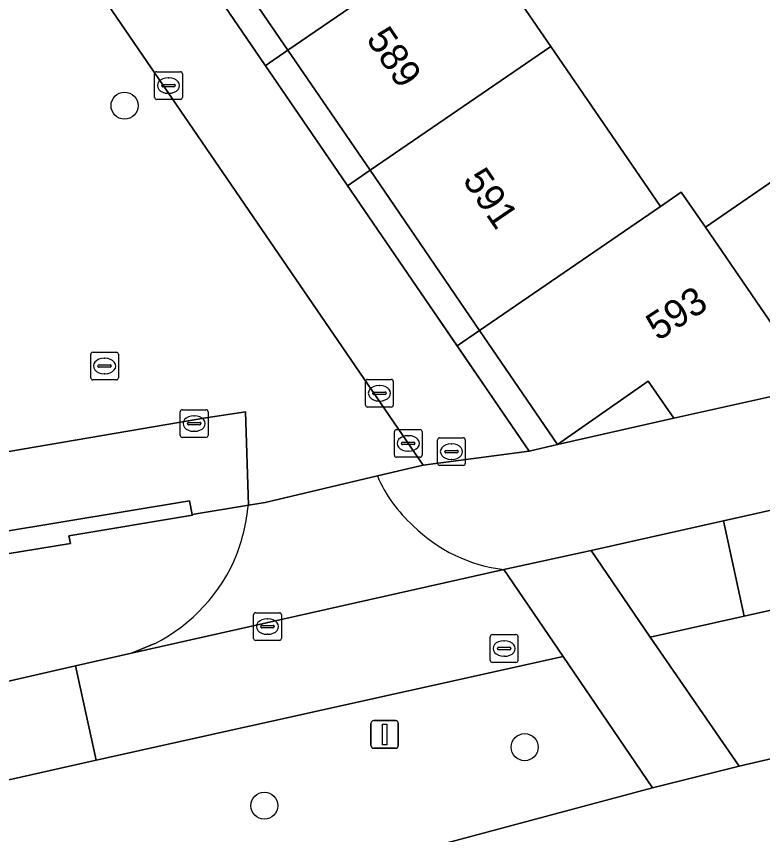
# Model space of a CAD drawing. Extents: x 155275 to 156265, y 382654 to 383635.
# Drawn here: x 155784.06 to 155810.99, y 383184.9 to 383214.43 of the extents above; entities that cross this region are included whole.
import ezdxf

# ---------------------------------------------------------------- set-up
doc = ezdxf.new("R2010")
doc.units = 0
for name, color, linetype in [('IMGEO_Berm_groen', 7, 'Continuous'), ('IMGEO_Boom', 7, 'Continuous'), ('IMGEO_Erf', 7, 'Continuous'), ('IMGEO_Fietspad_gesloten', 7, 'Continuous'), ('IMGEO_Kolk', 7, 'Continuous'), ('IMGEO_Pand', 7, 'Continuous'), ('IMGEO_Pand_nummerreeks', 7, 'Continuous'), ('IMGEO_Pand_overbouw', 7, 'Continuous'), ('IMGEO_Rijbaan_lokaal_gesloten', 7, 'Continuous'), ('IMGEO_Rijbaan_lokaal_open', 7, 'Continuous'), ('IMGEO_Rioolput', 7, 'Continuous'), ('IMGEO_Verkeersbordpaal', 7, 'Continuous'), ('IMGEO_Voetpad_op_trap', 7, 'Continuous'), ('IMGEO_Voetpad_open', 7, 'Continuous')]:
    doc.layers.add(name, color=color, linetype=linetype)

msp = doc.modelspace()

# ---------------------------------------------------------------- linework, layer by layer
at = {"layer": 'IMGEO_Berm_groen'}
msp.add_lwpolyline([(155848.276, 383195.813), (155845.025, 383200.548), (155840.331, 383199.496), (155810.33, 383192.781), (155806.938, 383192.022), (155810.141, 383187.373), (155824.371, 383190.683)], close=True, dxfattribs=at)
for points in [[(155807.023, 383186.593), (155803.798, 383191.327), (155786.939, 383187.587), (155780.617, 383186.169), (155774.297, 383184.74), (155766.281, 383182.536), (155758.269, 383180.313), (155752.351, 383178.024)], [(155758.942, 383174.226), (155784.144, 383180.465), (155807.023, 383186.593)]]:
    msp.add_lwpolyline(points, dxfattribs=at)
at = {"layer": 'IMGEO_Boom'}
for centre in [(155787.962, 383211.208), (155802.404, 383188.058), (155793.007, 383185.946)]:
    msp.add_circle(centre, 0.489, dxfattribs=at)
at = {"layer": 'IMGEO_Erf'}
for points in [[(155796.822, 383208.878), (155793.858, 383213.211), (155790.894, 383217.545), (155787.93, 383221.878), (155784.96, 383226.22), (155781.602, 383231.129), (155777.993, 383236.404), (155777.166, 383235.849), (155802.561, 383198.744), (155803.59, 383198.984), (155800.774, 383203.1)], [(155803.59, 383198.984), (155807.785, 383199.931), (155806.855, 383201.265)]]:
    msp.add_lwpolyline(points, close=True, dxfattribs=at)
msp.add_lwpolyline([(155800.38, 383217.68), (155803.347, 383213.349), (155807.304, 383207.574), (155808.057, 383208.09), (155808.925, 383206.823), (155812.132, 383209.02), (155812.697, 383208.195), (155816.162, 383210.569), (155817.448, 383208.691), (155821.408, 383211.404), (155821.973, 383210.579), (155824.618, 383212.391), (155825.438, 383212.953), (155823.731, 383215.445)], dxfattribs=at)
at = {"layer": 'IMGEO_Fietspad_gesloten'}
msp.add_lwpolyline([(155890.991, 383205.663), (155886.832, 383204.488), (155883.25, 383203.59), (155879.663, 383202.712), (155851.768, 383196.574), (155848.276, 383195.813), (155824.371, 383190.683), (155810.141, 383187.373), (155807.023, 383186.593), (155784.144, 383180.465), (155758.942, 383174.226)], dxfattribs=at)
at = {"layer": 'IMGEO_Kolk'}
for p, q in [((155789.048, 383211.508), (155789.048, 383212.36)), ((155789.123, 383212.434), (155789.975, 383212.434)), ((155790.049, 383212.36), (155790.049, 383211.508)), ((155789.536, 383212.214), (155789.561, 383212.214)), ((155789.307, 383211.928), (155789.307, 383211.94)), ((155789.745, 383211.891), (155789.347, 383211.891)), ((155789.35, 383211.977), (155789.748, 383211.977)), ((155789.791, 383211.94), (155789.791, 383211.928)), ((155789.559, 383211.654), (155789.534, 383211.654)), ((155789.975, 383211.434), (155789.123, 383211.434)), ((155786.815, 383202.312), (155787.667, 383202.312)), ((155786.74, 383201.386), (155786.74, 383202.238)), ((155787.228, 383202.092), (155787.253, 383202.092)), ((155787.741, 383202.238), (155787.741, 383201.386)), ((155786.999, 383201.806), (155786.999, 383201.818)), ((155787.437, 383201.769), (155787.039, 383201.769)), ((155787.042, 383201.855), (155787.44, 383201.855)), ((155787.483, 383201.818), (155787.483, 383201.806)), ((155787.251, 383201.532), (155787.226, 383201.532)), ((155787.667, 383201.312), (155786.815, 383201.312)), ((155796.66, 383200.404), (155796.66, 383201.256)), ((155796.735, 383201.33), (155797.587, 383201.33)), ((155797.148, 383201.11), (155797.173, 383201.11)), ((155797.661, 383201.256), (155797.661, 383200.404)), ((155796.919, 383200.824), (155796.919, 383200.836)), ((155796.962, 383200.873), (155797.36, 383200.873)), ((155797.403, 383200.836), (155797.403, 383200.824)), ((155797.357, 383200.787), (155796.959, 383200.787)), ((155797.171, 383200.55), (155797.146, 383200.55)), ((155790.048, 383200.236), (155790.9, 383200.236)), ((155797.587, 383200.33), (155796.735, 383200.33)), ((155789.973, 383199.31), (155789.973, 383200.162)), ((155790.461, 383200.016), (155790.486, 383200.016)), ((155790.974, 383200.162), (155790.974, 383199.31)), ((155790.232, 383199.73), (155790.232, 383199.742)), ((155790.67, 383199.693), (155790.272, 383199.693)), ((155790.275, 383199.779), (155790.673, 383199.779)), ((155790.716, 383199.742), (155790.716, 383199.73)), ((155790.484, 383199.456), (155790.459, 383199.456)), ((155790.9, 383199.236), (155790.048, 383199.236)), ((155792.696, 383192.91), (155793.548, 383192.91)), ((155792.621, 383191.984), (155792.621, 383192.836)), ((155793.109, 383192.69), (155793.134, 383192.69)), ((155793.622, 383192.836), (155793.622, 383191.984)), ((155792.88, 383192.404), (155792.88, 383192.416)), ((155793.318, 383192.367), (155792.92, 383192.367)), ((155792.923, 383192.453), (155793.321, 383192.453)), ((155793.364, 383192.416), (155793.364, 383192.404)), ((155793.132, 383192.13), (155793.107, 383192.13)), ((155793.548, 383191.91), (155792.696, 383191.91))]:
    msp.add_line(p, q, dxfattribs=at)
for points in [[(155789.048, 383211.508), (155789.048, 383212.36)], [(155789.123, 383212.434), (155789.975, 383212.434)], [(155790.049, 383212.36), (155790.049, 383211.508)], [(155789.975, 383211.434), (155789.123, 383211.434)], [(155786.815, 383202.312), (155787.667, 383202.312)], [(155786.74, 383201.386), (155786.74, 383202.238)], [(155787.741, 383202.238), (155787.741, 383201.386)], [(155787.667, 383201.312), (155786.815, 383201.312)], [(155796.66, 383200.404), (155796.66, 383201.256)], [(155796.735, 383201.33), (155797.587, 383201.33)], [(155797.661, 383201.256), (155797.661, 383200.404)], [(155790.048, 383200.236), (155790.9, 383200.236)], [(155797.587, 383200.33), (155796.735, 383200.33)], [(155789.973, 383199.31), (155789.973, 383200.162)], [(155790.974, 383200.162), (155790.974, 383199.31)], [(155790.9, 383199.236), (155790.048, 383199.236)], [(155792.696, 383192.91), (155793.548, 383192.91)], [(155792.621, 383191.984), (155792.621, 383192.836)], [(155793.622, 383192.836), (155793.622, 383191.984)], [(155793.548, 383191.91), (155792.696, 383191.91)]]:
    msp.add_lwpolyline(points, dxfattribs=at)
for centre, radius, start, end in [((155789.125, 383212.358), 0.0765, 91.552, 178.448), ((155789.125, 383212.358), 0.0765, 91.552, 178.448), ((155789.973, 383212.358), 0.0765, 1.552, 88.448), ((155789.973, 383212.358), 0.0765, 1.552, 88.448), ((155789.347, 383211.937), 0.0403, 85.8775, 175.7526), ((155789.344, 383211.927), 0.0366, 178.938, 274.7102), ((155789.748, 383211.934), 0.043, 264.8664, 352.4533), ((155789.752, 383211.939), 0.0386, 1.7309, 96.639), ((155789.125, 383211.51), 0.0765, 181.552, 268.448), ((155789.125, 383211.51), 0.0765, 181.552, 268.448), ((155789.973, 383211.51), 0.0765, 271.552, 358.448), ((155789.973, 383211.51), 0.0765, 271.552, 358.448), ((155786.817, 383202.236), 0.0765, 91.552, 178.448), ((155786.817, 383202.236), 0.0765, 91.552, 178.448), ((155787.665, 383202.236), 0.0765, 1.552, 88.448), ((155787.665, 383202.236), 0.0765, 1.552, 88.448), ((155787.039, 383201.815), 0.0403, 85.8775, 175.7526), ((155787.036, 383201.805), 0.0366, 178.938, 274.7102), ((155787.44, 383201.812), 0.043, 264.8664, 352.4533), ((155787.444, 383201.817), 0.0386, 1.7309, 96.639), ((155786.817, 383201.388), 0.0765, 181.552, 268.448), ((155786.817, 383201.388), 0.0765, 181.552, 268.448), ((155787.665, 383201.388), 0.0765, 271.552, 358.448), ((155787.665, 383201.388), 0.0765, 271.552, 358.448), ((155796.737, 383201.254), 0.0765, 91.552, 178.448), ((155796.737, 383201.254), 0.0765, 91.552, 178.448), ((155797.585, 383201.254), 0.0765, 1.552, 88.448), ((155797.585, 383201.254), 0.0765, 1.552, 88.448), ((155796.959, 383200.833), 0.0403, 85.8775, 175.7526), ((155796.956, 383200.823), 0.0366, 178.938, 274.7102), ((155797.36, 383200.83), 0.043, 264.8664, 352.4533), ((155797.364, 383200.835), 0.0386, 1.7309, 96.639), ((155790.05, 383200.16), 0.0765, 91.552, 178.448), ((155790.05, 383200.16), 0.0765, 91.552, 178.448), ((155790.898, 383200.16), 0.0765, 1.552, 88.448), ((155790.898, 383200.16), 0.0765, 1.552, 88.448), ((155796.737, 383200.406), 0.0765, 181.552, 268.448), ((155796.737, 383200.406), 0.0765, 181.552, 268.448), ((155797.585, 383200.406), 0.0765, 271.552, 358.448), ((155797.585, 383200.406), 0.0765, 271.552, 358.448), ((155790.272, 383199.739), 0.0403, 85.8775, 175.7526), ((155790.269, 383199.729), 0.0366, 178.938, 274.7102), ((155790.673, 383199.736), 0.043, 264.8664, 352.4533), ((155790.677, 383199.741), 0.0386, 1.7309, 96.639), ((155790.05, 383199.312), 0.0765, 181.552, 268.448), ((155790.05, 383199.312), 0.0765, 181.552, 268.448), ((155790.898, 383199.312), 0.0765, 271.552, 358.448), ((155790.898, 383199.312), 0.0765, 271.552, 358.448), ((155792.698, 383192.834), 0.0765, 91.552, 178.448), ((155792.698, 383192.834), 0.0765, 91.552, 178.448), ((155793.546, 383192.834), 0.0765, 1.552, 88.448), ((155793.546, 383192.834), 0.0765, 1.552, 88.448), ((155792.92, 383192.413), 0.0403, 85.8775, 175.7526), ((155792.917, 383192.403), 0.0366, 178.938, 274.7102), ((155793.321, 383192.41), 0.043, 264.8664, 352.4533), ((155793.325, 383192.415), 0.0386, 1.7309, 96.639), ((155792.698, 383191.986), 0.0765, 181.552, 268.448), ((155792.698, 383191.986), 0.0765, 181.552, 268.448), ((155793.546, 383191.986), 0.0765, 271.552, 358.448), ((155793.546, 383191.986), 0.0765, 271.552, 358.448)]:
    msp.add_arc(centre, radius, start, end, dxfattribs=at)
for centre, major_axis, ratio, start_param, end_param in [((155789.535, 383211.934), (-0.387, 0.002), 0.722429, 4.712389, 7.853982), ((155789.56, 383211.934), (-0.39, 0.002), 0.717154, 1.570796, 4.712389), ((155787.227, 383201.812), (-0.387, 0.002), 0.722429, 4.712389, 7.853982), ((155787.252, 383201.812), (-0.39, 0.002), 0.717154, 1.570796, 4.712389), ((155797.147, 383200.83), (-0.387, 0.002), 0.722429, 4.712389, 7.853982), ((155797.172, 383200.83), (-0.39, 0.002), 0.717154, 1.570796, 4.712389), ((155790.46, 383199.736), (-0.387, 0.002), 0.722429, 4.712389, 7.853982), ((155790.485, 383199.736), (-0.39, 0.002), 0.717154, 1.570796, 4.712389), ((155793.108, 383192.41), (-0.387, 0.002), 0.722429, 4.712389, 7.853982), ((155793.133, 383192.41), (-0.39, 0.002), 0.717154, 1.570796, 4.712389)]:
    msp.add_ellipse(centre, major_axis=major_axis, ratio=ratio, start_param=start_param, end_param=end_param, dxfattribs=at)
at = {"layer": 'IMGEO_Pand'}
for points in [[(155793.858, 383213.211), (155800.38, 383217.68), (155797.413, 383222.011), (155790.894, 383217.545)], [(155793.858, 383213.211), (155796.822, 383208.878), (155803.347, 383213.349), (155800.38, 383217.68)], [(155803.347, 383213.349), (155796.822, 383208.878), (155800.774, 383203.1), (155807.304, 383207.574)], [(155817.448, 383208.691), (155816.162, 383210.569), (155812.697, 383208.195), (155812.132, 383209.02), (155808.925, 383206.823), (155812.872, 383201.064), (155816.423, 383203.531), (155817.361, 383202.086), (155821.253, 383202.95)], [(155808.925, 383206.823), (155808.057, 383208.09), (155807.304, 383207.574), (155800.774, 383203.1), (155803.59, 383198.984), (155806.855, 383201.265), (155807.785, 383199.931), (155812.872, 383201.064)]]:
    msp.add_lwpolyline(points, close=True, dxfattribs=at)
at = {"layer": 'IMGEO_Pand_overbouw'}
for points in [[(155793.858, 383213.211), (155790.894, 383217.545), (155790.077, 383216.985), (155793.042, 383212.652)], [(155793.858, 383213.211), (155793.042, 383212.652), (155796.007, 383208.32), (155796.822, 383208.878)], [(155800.774, 383203.1), (155796.822, 383208.878), (155796.007, 383208.32), (155799.961, 383202.543)], [(155800.774, 383203.1), (155799.961, 383202.543), (155802.561, 383198.744), (155803.59, 383198.984)], [(155803.59, 383198.984), (155807.785, 383199.931), (155806.855, 383201.265)]]:
    msp.add_lwpolyline(points, close=True, dxfattribs=at)
at = {"layer": 'IMGEO_Rijbaan_lokaal_gesloten'}
msp.add_lwpolyline([(155840.331, 383199.496), (155839.534, 383202.939), (155809.577, 383196.225), (155810.33, 383192.781)], close=True, dxfattribs=at)
msp.add_lwpolyline([(155752.351, 383178.024), (155758.269, 383180.313), (155766.281, 383182.536), (155774.297, 383184.74), (155780.617, 383186.169), (155786.939, 383187.587), (155786.191, 383190.995), (155778.526, 383189.242), (155770.862, 383187.481), (155761.516, 383184.966), (155752.173, 383182.442)], dxfattribs=at)
at = {"layer": 'IMGEO_Rijbaan_lokaal_open'}
for points in [[(155789.533, 383282.828), (155777.762, 383266.885), (155770.477, 383257.018), (155750.942, 383230.559), (155753.136, 383227.355), (155767.095, 383206.967), (155771.224, 383200.936), (155773.915, 383197.049), (155790.895, 383199.943), (155792.328, 383200.159), (155792.43, 383196.787), (155793.032, 383196.885), (155797.086, 383197.846), (155798.734, 383198.236), (155786.907, 383215.526), (155772.43, 383236.689), (155783.237, 383244.091), (155793.514, 383251.129), (155807.738, 383260.872), (155811.353, 383255.588), (155821.26, 383241.107), (155827.482, 383232.012), (155843.488, 383208.615)], [(155797.086, 383197.846), (155793.032, 383196.885)], [(155793.032, 383196.885), (155792.43, 383196.787)], [(155788.207, 383191.448), (155801.654, 383194.468)], [(155789.06, 383191.794), (155788.207, 383191.448)]]:
    msp.add_lwpolyline(points, dxfattribs=at)
for points in [[(155804.8, 383195.157), (155806.938, 383192.022), (155810.33, 383192.781), (155809.577, 383196.225)], [(155801.654, 383194.468), (155788.207, 383191.448), (155786.191, 383190.995), (155786.939, 383187.587), (155803.798, 383191.327)]]:
    msp.add_lwpolyline(points, close=True, dxfattribs=at)
for centre, radius, start, end in [((155801.701, 383199.811), 5.016, 203.058, 228.5824), ((155784.943, 383197.609), 7.532, 339.8726, 353.7365), ((155802.297, 383199.973), 5.542, 225.0712, 263.3362), ((155786.198, 383197.385), 6.281, 297.1127, 337.8551)]:
    msp.add_arc(centre, radius, start, end, dxfattribs=at)
at = {"layer": 'IMGEO_Rioolput'}
for p, q in [((155797.701, 383198.593), (155797.701, 383199.445)), ((155797.776, 383199.519), (155798.628, 383199.519)), ((155798.702, 383199.445), (155798.702, 383198.593)), ((155798.003, 383199.062), (155798.401, 383199.062)), ((155798.189, 383199.299), (155798.214, 383199.299)), ((155799.259, 383198.298), (155799.259, 383199.15)), ((155799.334, 383199.224), (155800.186, 383199.224)), ((155800.26, 383199.15), (155800.26, 383198.298)), ((155797.96, 383199.013), (155797.96, 383199.025)), ((155798.398, 383198.976), (155798, 383198.976)), ((155798.444, 383199.025), (155798.444, 383199.013)), ((155799.561, 383198.767), (155799.959, 383198.767)), ((155799.747, 383199.004), (155799.772, 383199.004)), ((155798.628, 383198.519), (155797.776, 383198.519)), ((155798.212, 383198.739), (155798.187, 383198.739)), ((155799.518, 383198.718), (155799.518, 383198.73)), ((155799.956, 383198.681), (155799.558, 383198.681)), ((155800.002, 383198.73), (155800.002, 383198.718)), ((155800.186, 383198.224), (155799.334, 383198.224)), ((155799.77, 383198.444), (155799.745, 383198.444)), ((155801.161, 383191.192), (155801.161, 383192.044)), ((155801.236, 383192.118), (155802.088, 383192.118)), ((155802.162, 383192.044), (155802.162, 383191.192)), ((155801.463, 383191.661), (155801.861, 383191.661)), ((155801.649, 383191.898), (155801.674, 383191.898)), ((155801.42, 383191.612), (155801.42, 383191.624)), ((155801.858, 383191.575), (155801.46, 383191.575)), ((155801.904, 383191.624), (155801.904, 383191.612)), ((155802.088, 383191.118), (155801.236, 383191.118)), ((155801.672, 383191.338), (155801.647, 383191.338))]:
    msp.add_line(p, q, dxfattribs=at)
for points in [[(155797.701, 383198.593), (155797.701, 383199.445)], [(155797.776, 383199.519), (155798.628, 383199.519)], [(155798.702, 383199.445), (155798.702, 383198.593)], [(155799.259, 383198.298), (155799.259, 383199.15)], [(155799.334, 383199.224), (155800.186, 383199.224)], [(155800.26, 383199.15), (155800.26, 383198.298)], [(155798.628, 383198.519), (155797.776, 383198.519)], [(155800.186, 383198.224), (155799.334, 383198.224)], [(155801.161, 383191.192), (155801.161, 383192.044)], [(155801.236, 383192.118), (155802.088, 383192.118)], [(155802.162, 383192.044), (155802.162, 383191.192)], [(155802.088, 383191.118), (155801.236, 383191.118)]]:
    msp.add_lwpolyline(points, dxfattribs=at)
for centre, radius, start, end in [((155797.778, 383199.443), 0.0765, 91.552, 178.448), ((155797.778, 383199.443), 0.0765, 91.552, 178.448), ((155798.626, 383199.443), 0.0765, 1.552, 88.448), ((155798.626, 383199.443), 0.0765, 1.552, 88.448), ((155798, 383199.022), 0.0403, 85.8775, 175.7526), ((155798.405, 383199.024), 0.0386, 1.7309, 96.639), ((155799.336, 383199.148), 0.0765, 91.552, 178.448), ((155799.336, 383199.148), 0.0765, 91.552, 178.448), ((155800.184, 383199.148), 0.0765, 1.552, 88.448), ((155800.184, 383199.148), 0.0765, 1.552, 88.448), ((155797.997, 383199.012), 0.0366, 178.938, 274.7102), ((155798.401, 383199.019), 0.043, 264.8664, 352.4533), ((155799.558, 383198.727), 0.0403, 85.8775, 175.7526), ((155799.963, 383198.729), 0.0386, 1.7309, 96.639), ((155797.778, 383198.595), 0.0765, 181.552, 268.448), ((155797.778, 383198.595), 0.0765, 181.552, 268.448), ((155798.626, 383198.595), 0.0765, 271.552, 358.448), ((155798.626, 383198.595), 0.0765, 271.552, 358.448), ((155799.555, 383198.717), 0.0366, 178.938, 274.7102), ((155799.959, 383198.724), 0.043, 264.8664, 352.4533), ((155799.336, 383198.3), 0.0765, 181.552, 268.448), ((155799.336, 383198.3), 0.0765, 181.552, 268.448), ((155800.184, 383198.3), 0.0765, 271.552, 358.448), ((155800.184, 383198.3), 0.0765, 271.552, 358.448), ((155801.238, 383192.042), 0.0765, 91.552, 178.448), ((155801.238, 383192.042), 0.0765, 91.552, 178.448), ((155802.086, 383192.042), 0.0765, 1.552, 88.448), ((155802.086, 383192.042), 0.0765, 1.552, 88.448), ((155801.46, 383191.621), 0.0403, 85.8775, 175.7526), ((155801.865, 383191.623), 0.0386, 1.7309, 96.639), ((155801.457, 383191.611), 0.0366, 178.938, 274.7102), ((155801.861, 383191.618), 0.043, 264.8664, 352.4533), ((155801.238, 383191.194), 0.0765, 181.552, 268.448), ((155801.238, 383191.194), 0.0765, 181.552, 268.448), ((155802.086, 383191.194), 0.0765, 271.552, 358.448), ((155802.086, 383191.194), 0.0765, 271.552, 358.448)]:
    msp.add_arc(centre, radius, start, end, dxfattribs=at)
for centre, major_axis, ratio, start_param, end_param in [((155798.188, 383199.019), (-0.387, 0.002), 0.722429, 4.712389, 7.853982), ((155798.213, 383199.019), (-0.39, 0.002), 0.717154, 1.570796, 4.712389), ((155799.746, 383198.724), (-0.387, 0.002), 0.722429, 4.712389, 7.853982), ((155799.771, 383198.724), (-0.39, 0.002), 0.717154, 1.570796, 4.712389), ((155801.648, 383191.618), (-0.387, 0.002), 0.722429, 4.712389, 7.853982), ((155801.673, 383191.618), (-0.39, 0.002), 0.717154, 1.570796, 4.712389)]:
    msp.add_ellipse(centre, major_axis=major_axis, ratio=ratio, start_param=start_param, end_param=end_param, dxfattribs=at)
at = {"layer": 'IMGEO_Verkeersbordpaal'}
for p, q in [((155796.953, 383189.016), (155797.743, 383189.016)), ((155797.743, 383189.016), (155796.953, 383189.016)), ((155796.853, 383188.116), (155796.853, 383188.916)), ((155796.853, 383188.916), (155796.853, 383188.116)), ((155797.843, 383188.916), (155797.843, 383188.116)), ((155797.843, 383188.116), (155797.843, 383188.916)), ((155797.743, 383188.016), (155796.953, 383188.016)), ((155796.953, 383188.016), (155797.743, 383188.016))]:
    msp.add_line(p, q, dxfattribs=at)
msp.add_lwpolyline([(155797.273, 383188.891), (155797.423, 383188.891), (155797.423, 383188.141), (155797.273, 383188.141), (155797.273, 383188.891)], dxfattribs=at)
for centre, start, end in [((155796.953, 383188.916), 90, 180), ((155796.953, 383188.916), 90, 180), ((155797.743, 383188.916), 0, 90), ((155797.743, 383188.916), 360, 90), ((155796.953, 383188.116), 180, 270), ((155796.953, 383188.116), 180, 270), ((155797.743, 383188.116), 270, 0), ((155797.743, 383188.116), 270, 0)]:
    msp.add_arc(centre, 0.1, start, end, dxfattribs=at)
at = {"layer": 'IMGEO_Voetpad_op_trap'}
msp.add_lwpolyline([(155779.154, 383193.982), (155782.598, 383194.561), (155782.535, 383194.838), (155786.008, 383195.413), (155785.955, 383195.688), (155790.411, 383196.43), (155790.405, 383196.458), (155790.308, 383196.944), (155771.936, 383193.905), (155773.013, 383192.332), (155775.211, 383192.757), (155775.154, 383193.012), (155779.197, 383193.704)], close=True, dxfattribs=at)
at = {"layer": 'IMGEO_Voetpad_open'}
for points in [[(155772.43, 383236.689), (155786.907, 383215.526), (155798.734, 383198.236), (155802.561, 383198.744), (155777.166, 383235.849)], [(155849.412, 383209.926), (155843.488, 383208.615), (155840.374, 383207.229), (155839.315, 383206.997), (155834.384, 383205.895), (155829.654, 383204.83), (155825.834, 383203.977), (155821.253, 383202.95), (155817.361, 383202.086), (155812.872, 383201.064), (155807.785, 383199.931), (155803.59, 383198.984), (155802.561, 383198.744), (155798.734, 383198.236), (155797.086, 383197.846)], [(155801.654, 383194.468), (155804.8, 383195.157), (155809.577, 383196.225), (155839.534, 383202.939)], [(155771.936, 383193.905), (155790.308, 383196.944), (155790.405, 383196.458), (155792.43, 383196.787), (155792.328, 383200.159), (155790.895, 383199.943), (155773.915, 383197.049)], [(155792.43, 383196.787), (155790.405, 383196.458), (155790.411, 383196.43), (155785.955, 383195.688), (155786.008, 383195.413), (155782.535, 383194.838), (155782.598, 383194.561), (155779.154, 383193.982), (155779.197, 383193.704), (155775.154, 383193.012), (155775.211, 383192.757), (155773.013, 383192.332), (155773.14, 383192.147), (155762.885, 383189.376), (155755.193, 383186.963), (155754.924, 383188.287), (155752.587, 383187.808), (155749.371, 383187.133), (155749.124, 383187.081)], [(155786.191, 383190.995), (155788.207, 383191.448), (155789.06, 383191.794)], [(155752.173, 383182.442), (155761.516, 383184.966), (155770.862, 383187.481), (155778.526, 383189.242), (155786.191, 383190.995)]]:
    msp.add_lwpolyline(points, dxfattribs=at)
msp.add_lwpolyline([(155803.798, 383191.327), (155807.023, 383186.593), (155810.141, 383187.373), (155806.938, 383192.022), (155804.8, 383195.157), (155801.654, 383194.468)], close=True, dxfattribs=at)
for centre, radius, start, end in [((155801.701, 383199.811), 5.016, 203.058, 228.5824), ((155784.943, 383197.609), 7.532, 339.8726, 353.7365), ((155802.297, 383199.973), 5.542, 225.0712, 263.3362), ((155786.198, 383197.385), 6.281, 297.1127, 337.8551)]:
    msp.add_arc(centre, radius, start, end, dxfattribs=at)

# ---------------------------------------------------------------- texts
at = {"layer": 'IMGEO_Pand_nummerreeks'}
for s, rotation, p in [('589', 304.3151, (155796.657, 383213.61)), ('591', 304.2236, (155800.141, 383208.52)), ('593', 32.967, (155807.214, 383202.696))]:
    msp.add_text(s, height=1, rotation=rotation, dxfattribs=at).set_placement(p)

doc.saveas('drawing.dxf')
